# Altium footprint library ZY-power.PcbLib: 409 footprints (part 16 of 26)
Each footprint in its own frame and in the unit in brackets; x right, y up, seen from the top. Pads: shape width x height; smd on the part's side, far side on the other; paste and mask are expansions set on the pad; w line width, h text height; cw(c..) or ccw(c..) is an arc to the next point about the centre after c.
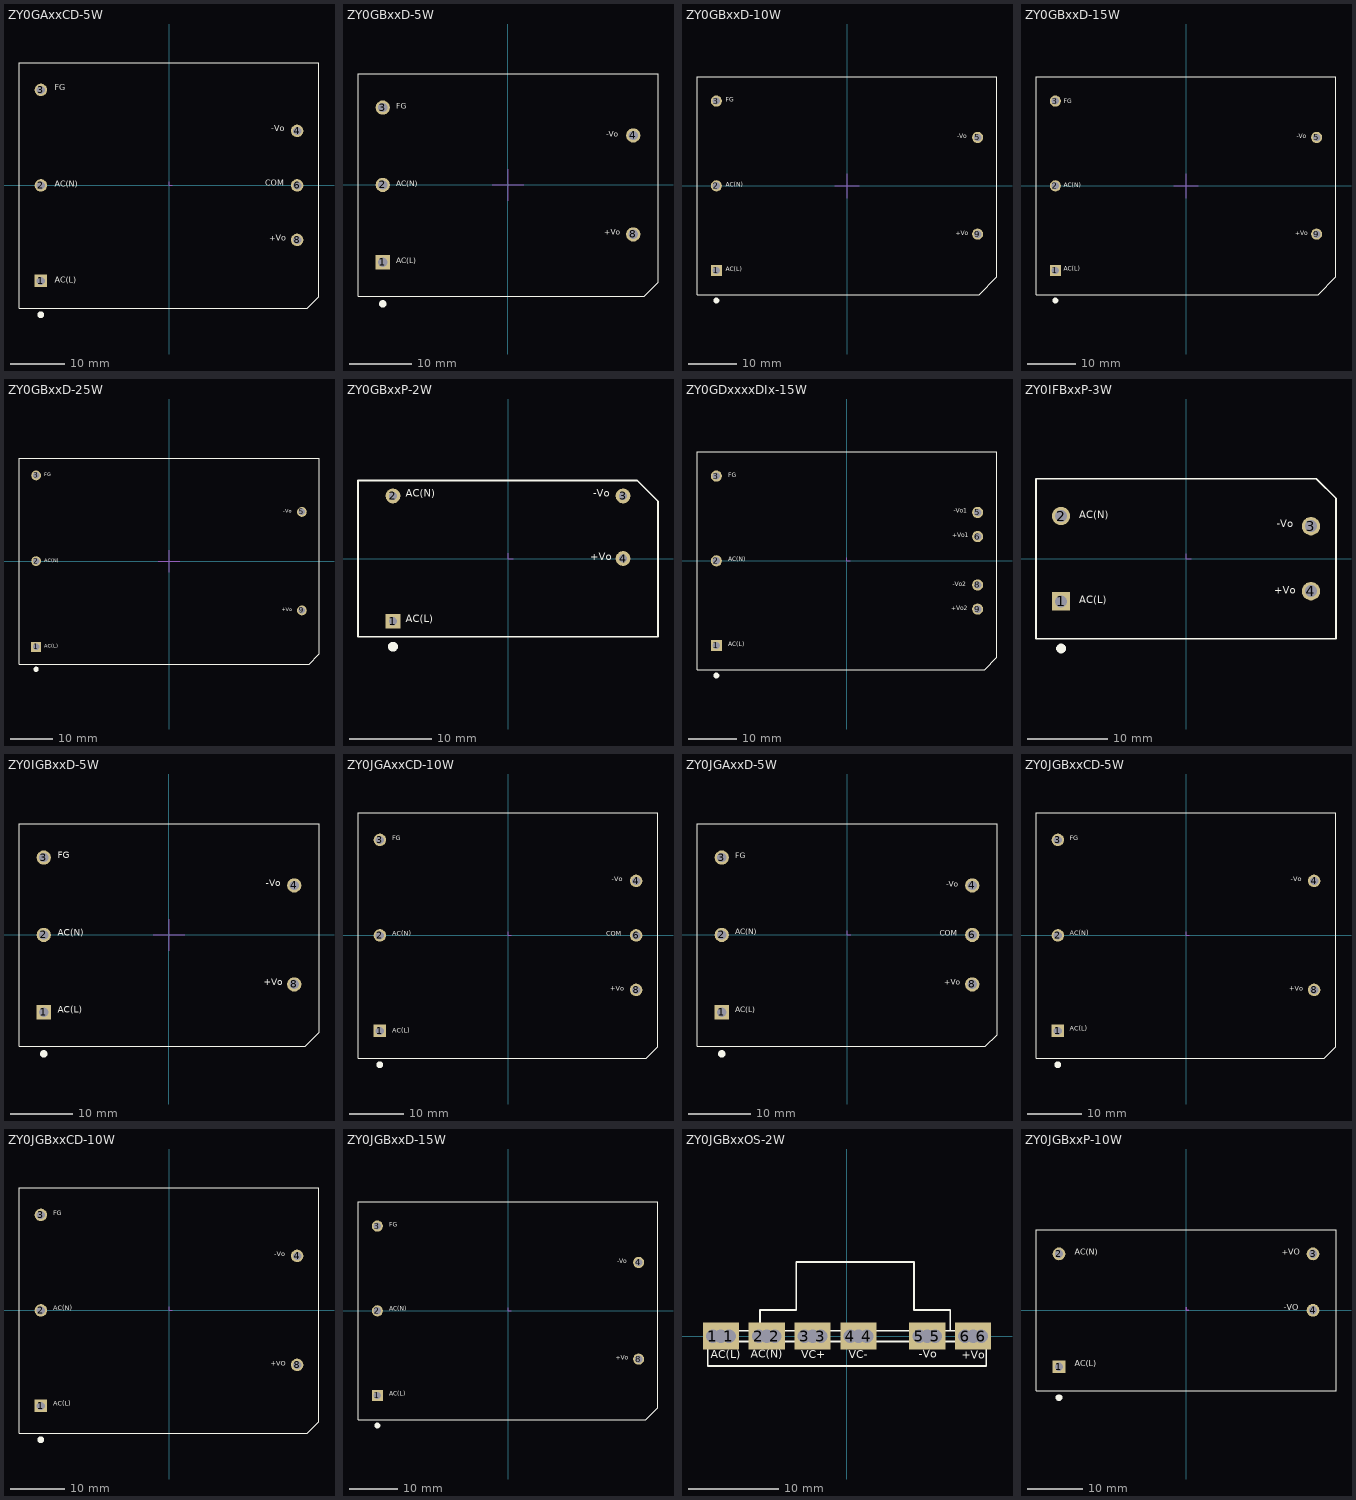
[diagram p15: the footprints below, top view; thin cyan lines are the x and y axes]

## ZY0GAxxCD-5W [mm]
height 20.5
pads (6):
  rect 2.3x2.3 hole 1.5: 1(-23.5,-17.5)
  round 2.3 hole 1.5: 2(-23.5,0) 3(-23.5,17.5) 4(23.5,10) 6(23.5,0) 8(23.5,-10)
Top Overlay:
  circle w1: c-23.5,-23.725 r0.1
  lines w0.2: -27.5,-22.5 -27.5,22.5 27.5,22.5 27.5,-20.379 25.379,-22.5 -27.5,-22.5
  text "AC(L)" at -20.96,-18.186 h1.78
  text "AC(N)" at -20.96,-0.572 h1.78
  text "FG" at -20.96,17.043 h1.78
  text "+Vo" at 18.343,-10.541 h1.78
  text "COM" at 17.658,-0.457 h1.78
  text "-Vo" at 18.768,9.601 h1.78
Mechanical 15:
  lines w0.127: 0,0.635 0,0 0.635,0

## ZY0GBxxD-5W [mm] "120426 修改 by kong"
height 20
pads (5):
  rect 2.3x2.3 hole 1.5: 1(-20.25,-12.5)
  round 2.3 hole 1.5: 2(-20.25,0) 3(-20.25,12.5) 4(20.25,8) 8(20.25,-8)
Top Overlay:
  circle w1: c-20.25,-19.225 r0.1
  lines w0.2: 22.033,-18 -24.25,-18 -24.25,18 24.25,18 24.25,-15.773 22.033,-17.991
  text "AC(L)" at -18.091,-13.008 h1.52
  text "AC(N)" at -18.091,-0.562 h1.52
  text "FG" at -18.091,12.011 h1.52
  text "+Vo" at 15.551,-8.381 h1.52
  text "-Vo" at 15.863,7.439 h1.52
Mechanical 15:
  lines w0.152: -2.54,0 2.54,0 ; 0,-2.54 0,2.54

## ZY0GBxxD-10W [mm] "120426 修改 by kong"
height 22.5
pads (5):
  rect 2.3x2.3 hole 1.5: 1(-27,-17.5)
  round 2.3 hole 1.5: 2(-27,0) 3(-27,17.5) 5(27,10) 9(27,-10)
Top Overlay:
  circle w1: c-27,-23.725 r0.1
  lines w0.2: -31,-22.5 27.325,-22.5 31,-18.825 31,22.5 -31,22.5 -31,-22.5
  text "AC(L)" at -25.095,-18.008 h1.52
  text "AC(N)" at -25.095,-0.482 h1.52
  text "FG" at -25.095,17.044 h1.52
  text "+Vo" at 22.428,-10.508 h1.52
  text "-Vo" at 22.74,9.558 h1.52
Mechanical 15:
  lines w0.152: -2.54,0 2.54,0 ; 0,-2.54 0,2.54

## ZY0GBxxD-15W [mm] "120426 修改 by kong"
height 22.5
pads (5):
  rect 2.3x2.3 hole 1.5: 1(-27,-17.5)
  round 2.3 hole 1.5: 2(-27,0) 3(-27,17.5) 5(27,10) 9(27,-10)
Top Overlay:
  circle w1: c-27,-23.725 r0.1
  lines w0.2: -31,-22.5 27.325,-22.5 31,-18.825 31,22.5 -31,22.5 -31,-22.5
  text "AC(L)" at -25.222,-17.881 h1.52
  text "AC(N)" at -25.222,-0.609 h1.52
  text "FG" at -25.222,16.79 h1.52
  text "+Vo" at 22.555,-10.508 h1.52
  text "-Vo" at 22.867,9.525 h1.52
Mechanical 15:
  lines w0.152: -2.54,0 2.54,0 ; 0,-2.54 0,2.54

## ZY0GBxxD-25W [mm] "120426 修改 by kong"
height 23.5
pads (5):
  rect 2.3x2.3 hole 1.5: 1(-31,-20)
  round 2.3 hole 1.5: 2(-31,0) 3(-31,20) 5(31,11.5) 9(31,-11.5)
Top Overlay:
  circle w1: c-31,-25.225 r0.1
  lines w0.2: -35,-24 -35,24 35,24 35,-21.691 32.691,-24 -35,-24
  text "-Vo" at 26.613,10.988 h1.52
  text "+Vo" at 26.301,-11.999 h1.52
  text "FG" at -29.095,19.497 h1.52
  text "AC(N)" at -29.095,-0.569 h1.52
  text "AC(L)" at -29.095,-20.508 h1.52
Mechanical 15:
  lines w0.152: -2.54,0 2.54,0 ; 0,-2.54 0,2.54

## ZY0GBxxP-2W [mm]
height 17
pads (4):
  rect 1.8x1.8 hole 1: 1(-14,-7.62)
  round 1.8 hole 1: 2(-14,7.62) 3(14,7.62) 4(14,0)
Top Overlay:
  circle w1: c-14,-10.725 r0.1
  lines w0.2: -18.25,-9.5 -18.25,9.5 15.71,9.5 18.25,6.96 18.25,-9.5 -18.25,-9.5
  text "AC(N)" at -12.446,7.188 h1.52
  text "-Vo" at 10.345,7.214 h1.52
  text "+Vo" at 10.033,-0.483 h1.52
  text "AC(L)" at -12.446,-8.026 h1.52
Mechanical 15:
  lines w0.127: 0,0.635 0,0 0.635,0

## ZY0GDxxxxDIx-15W [mm]
height 22.5
pads (7):
  rect 2.3x2.3 hole 1.5: 1(-27,-17.5)
  round 2.3 hole 1.5: 2(-27,0) 3(-27,17.5) 5(27,10) 6(27,5) 8(27,-5) 9(27,-10)
Top Overlay:
  circle w1: c-27,-23.725 r0.1
  lines w0.2: -31,-22.5 28.478,-22.5 31,-19.978 31,22.5 -31,22.5 -31,-22.5
  text "+Vo2" at 21.539,-10.566 h1.52
  text "-Vo2" at 21.851,-5.566 h1.52
  text "+Vo1" at 21.717,4.594 h1.52
  text "-Vo1" at 22.029,9.576 h1.52
  text "AC(L)" at -24.587,-17.932 h1.52
  text "AC(N)" at -24.587,-0.406 h1.52
  text "FG" at -24.587,16.993 h1.52
Mechanical 15:
  lines w0.127: 0,0.635 0,0 0.635,0

## ZY0IFBxxP-3W [mm]
pads (4):
  rect 2.3x2.3 hole 1.5: 1(-15.62,-5.335)
  round 2.3 hole 1.5: 2(-15.62,5.335) 3(15.62,4.065) 4(15.62,-4.065)
Top Overlay:
  circle w1: c-15.62,-11.225 r0.1
  lines w0.2: -18.75,-10 18.75,-10 18.75,7.539 16.289,10 -18.75,10 -18.75,-10
  text "+Vo" at 11.048,-4.666 h1.52
  text "-Vo" at 11.36,3.589 h1.52
  text "AC(N)" at -13.334,4.775 h1.52
  text "AC(L)" at -13.334,-5.893 h1.52
Mechanical 15:
  lines w0.127: 0,0.635 0,0 0.635,0

## ZY0IGBxxD-5W [mm] "120426 修改 by kong"
height 20
pads (5):
  rect 2.3x2.3 hole 1.5: 1(-20.25,-12.5)
  round 2.3 hole 1.5: 2(-20.25,0) 3(-20.25,12.5) 4(20.25,8) 8(20.25,-8)
Top Overlay:
  circle w1: c-20.255,-19.225 r0.1
  lines w0.2: 22.033,-18 -24.25,-18 -24.25,18 24.25,18 24.25,-15.773 22.033,-17.991
  text "-Vo" at 15.661,7.439 h1.78
  text "+Vo" at 15.297,-8.563 h1.78
  text "FG" at -17.964,12.011 h1.78
  text "AC(N)" at -17.964,-0.562 h1.78
  text "AC(L)" at -17.964,-13.008 h1.78
Mechanical 15:
  lines w0.152: -2.54,0 2.54,0 ; 0,-2.54 0,2.54

## ZY0JGAxxCD-10W [mm]
height 20.5
pads (6):
  rect 2.3x2.3 hole 1.5: 1(-23.5,-17.5)
  round 2.3 hole 1.5: 2(-23.5,0) 3(-23.5,17.5) 4(23.5,10) 6(23.5,0) 8(23.5,-10)
Top Overlay:
  circle w1: c-23.5,-23.725 r0.1
  lines w0.2: -27.5,-22.5 -27.5,22.5 27.5,22.5 27.5,-20.379 25.379,-22.5 -27.5,-22.5
  text "AC(L)" at -21.214,-18.186 h1.52
  text "AC(N)" at -21.214,-0.445 h1.52
  text "FG" at -21.214,17.043 h1.52
  text "+Vo" at 18.708,-10.541 h1.52
  text "COM" at 18.039,-0.457 h1.52
  text "-Vo" at 19.02,9.601 h1.52
Mechanical 15:
  lines w0.127: 0,0.635 0,0 0.635,0

## ZY0JGAxxD-5W [mm]
height 20.5
pads (6):
  rect 2.3x2.3 hole 1.5: 1(-20.25,-12.5)
  round 2.3 hole 1.5: 2(-20.25,0) 3(-20.25,12.5) 4(20.25,8) 6(20.25,0) 8(20.25,-8)
Top Overlay:
  circle w1: c-20.25,-19.225 r0.1
  lines w0.2: -24.25,-18 -24.25,18 24.25,18 24.25,-16.136 22.386,-18 -24.25,-18
  text "-Vo" at 16.011,7.493 h1.52
  text "+Vo" at 15.699,-8.382 h1.52
  text "FG" at -18.034,12.065 h1.52
  text "AC(N)" at -18.034,-0.229 h1.52
  text "AC(L)" at -18.034,-12.827 h1.52
  text "COM" at 15.03,-0.445 h1.52
Mechanical 15:
  lines w0.127: 0,0.635 0,0 0.635,0

## ZY0JGBxxCD-5W [mm]
pads (5):
  rect 2.3x2.3 hole 1.5: 1(-23.5,-17.5)
  round 2.3 hole 1.5: 2(-23.5,0) 3(-23.5,17.5) 4(23.5,10) 8(23.5,-10)
Top Overlay:
  circle w1: c-23.5,-23.725 r0.1
  lines w0.2: -27.5,-22.5 -27.5,22.5 27.5,22.5 27.5,-20.379 25.379,-22.5 -27.5,-22.5
  text "AC(L)" at -21.341,-17.882 h1.52
  text "AC(N)" at -21.341,-0.356 h1.52
  text "FG" at -21.341,17.043 h1.52
  text "+Vo" at 18.928,-10.516 h1.52
  text "-Vo" at 19.24,9.55 h1.52
Mechanical 15:
  lines w0.127: 0,0.635 0,0 0.635,0

## ZY0JGBxxCD-10W [mm]
pads (5):
  rect 2.3x2.3 hole 1.5: 1(-23.5,-17.5)
  round 2.3 hole 1.5: 2(-23.5,0) 3(-23.5,17.5) 4(23.5,10) 8(23.5,-10)
Top Overlay:
  circle w1: c-23.5,-23.725 r0.1
  lines w0.2: -27.5,-22.5 25.379,-22.5 27.5,-20.379 27.5,22.5 -27.5,22.5 -27.5,-22.5
  text "-Vo" at 19.277,9.55 h1.52
  text "+VO" at 18.674,-10.516 h1.52
  text "FG" at -21.214,17.043 h1.52
  text "AC(N)" at -21.214,-0.356 h1.52
  text "AC(L)" at -21.214,-17.882 h1.52
Mechanical 15:
  lines w0.127: 0,0.635 0,0 0.635,0

## ZY0JGBxxD-15W [mm]
height 22.5
pads (5):
  rect 2.3x2.3 hole 1.5: 1(-27,-17.5)
  round 2.3 hole 1.5: 2(-27,0) 3(-27,17.5) 4(27,10) 8(27,-10)
Top Overlay:
  circle w1: c-27,-23.725 r0.1
  lines w0.2: -31,-22.5 28.503,-22.5 31,-20.003 31,22.5 -31,22.5 -31,-22.5
  text "-Vo" at 22.588,9.55 h1.52
  text "+Vo" at 22.276,-10.389 h1.52
  text "FG" at -24.592,17.043 h1.52
  text "AC(N)" at -24.592,-0.267 h1.52
  text "AC(L)" at -24.592,-17.882 h1.52
Mechanical 15:
  lines w0.127: 0,0.635 0,0 0.635,0

## ZY0JGBxxOS-2W [mm]
height 17.2
pads (18):
  rect 2.2x3 hole 1.5 square: 1(-14.868,0) 1(-13.072,0) 2(-9.788,0) 2(-7.992,0) 3(-4.708,0) 3(-2.912,0) 4(0.372,0) 4(2.168,0) 5(7.992,0) 5(9.788,0) 6(13.072,0) 6(14.868,0)
  round 0 hole 1.5 square: 1(-13.967,0) 2(-8.887,0) 3(-3.807,0) 4(1.273,0) 5(8.893,0) 6(13.973,0)
Top Overlay:
  lines w0.2: -15.417,-0.6 0.003,-0.6 15.423,-0.6 ; -9.627,0.6 -9.627,2.9 -5.627,2.9 -5.627,8.2 7.432,8.2 7.432,2.9 11.432,2.9 11.432,0.6 ; -15.417,-3.3 0.003,-3.3 15.423,-3.3 15.423,0.6 0.003,0.6 -15.417,0.6 -15.417,-3.3
  text "AC(L)" at -15.083,-2.792 h1.52
  text "AC(N)" at -10.689,-2.741 h1.52
  text "VC+" at -5.075,-2.767 h1.52
  text "VC-" at 0.183,-2.792 h1.52
  text "-Vo" at 7.955,-2.716 h1.52
  text "+Vo" at 12.705,-2.817 h1.52

## ZY0JGBxxP-10W [mm]
height 19
pads (4):
  rect 2.3x2.3 hole 1.5: 1(-22.86,-10.16)
  round 2.3 hole 1.5: 2(-22.86,10.16) 3(22.86,10.16) 4(22.86,0)
Top Overlay:
  circle w1: c-22.86,-15.725 r0.1
  lines w0.1: -27,-14.5 -27,14.5 27,14.5 27,-14.5 -27,-14.5
  text "AC(L)" at -20.066,-10.414 h1.78
  text "AC(N)" at -20.066,9.652 h1.78
  text "+VO" at 17.272,9.674 h1.78
  text "-VO" at 17.636,-0.381 h1.78
Mechanical 15:
  lines w0.254: 0,0.508 0,0 0.508,0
